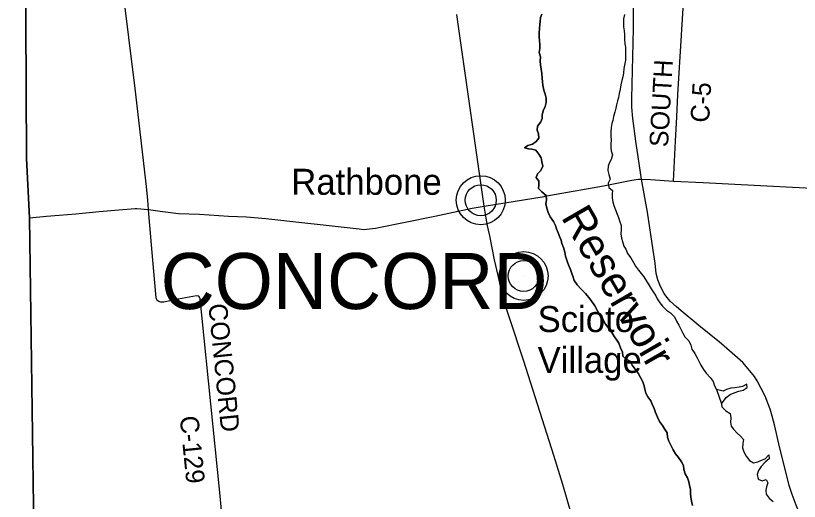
# Model space of a CAD drawing. Extents: x 1674899 to 2057726, y 653888 to 988278.
# Drawn here: x 1780755 to 1793352, y 795806 to 803604 of the extents above; entities that cross this region are included whole.
import ezdxf

# ---------------------------------------------------------------- set-up
doc = ezdxf.new("R2010")
doc.units = 0
for name, color, linetype in [('GM_X_Adjacent_County', 7, 'Continuous'), ('GM_X_County', 7, 'Continuous'), ('GM_X_County_Road', 7, 'Continuous'), ('GM_X_County_Road_Text', 7, 'Continuous'), ('GM_X_Major_Lake', 7, 'Continuous'), ('GM_X_Major_Lake_Text', 7, 'Continuous'), ('GM_X_Major_River', 7, 'Continuous'), ('GM_X_State_Route', 7, 'Continuous'), ('GM_X_Township', 7, 'Continuous'), ('GM_X_Township_Text', 7, 'Continuous'), ('GM_X_Unincorporated', 7, 'Continuous'), ('GM_X_Unincorporated_Location', 7, 'Continuous'), ('GM_X_Unincorporated_Text', 7, 'Continuous')]:
    doc.layers.add(name, color=color, linetype=linetype)

msp = doc.modelspace()

# ---------------------------------------------------------------- linework, layer by layer
at = {"layer": 'GM_X_Adjacent_County'}
msp.add_lwpolyline([(1780755, 818148), (1780889, 810163), (1780895, 808002), (1780927, 801312), (1780979, 800357), (1781040, 795733), (1781062, 793102), (1781083, 789921), (1781088, 789265), (1781086, 787507), (1781084, 787075), (1781136, 786470), (1781151, 786236), (1781162, 786094), (1781118, 783904)], dxfattribs=at)
at = {"layer": 'GM_X_County'}
msp.add_lwpolyline([(1781118, 783904), (1781162, 786094), (1781151, 786236), (1781136, 786470), (1781084, 787075), (1781086, 787507), (1781088, 789265), (1781083, 789921), (1781062, 793102), (1781040, 795733), (1780979, 800357), (1780927, 801312), (1780895, 808002), (1780889, 810163), (1780755, 818148)], dxfattribs=at)
at = {"layer": 'GM_X_County_Road'}
for points in [[(1782890, 800490), (1782881, 800644), (1782856, 800863), (1782676, 802437), (1782464, 804119), (1782395, 804661), (1782246, 805871), (1782006, 808105), (1781669, 811078), (1781659, 811109), (1781650, 811131), (1781636, 811151)], [(1791328, 800949), (1791359, 801588), (1791381, 801980), (1791400, 802336), (1791517, 804248), (1791555, 804839), (1791576, 805255), (1791663, 806861), (1791666, 806898), (1791673, 806996), (1791713, 807764)], [(1790259, 800884), (1790662, 800965), (1790767, 800980), (1790816, 800981)], [(1790816, 800981), (1790957, 800973), (1791328, 800949), (1791805, 800926), (1792317, 800900), (1794586, 800781), (1795455, 800738), (1796520, 800687)], [(1789248, 800701), (1789260, 800704), (1790202, 800872), (1790259, 800884)], [(1788284, 800545), (1789248, 800701)], [(1780979, 800357), (1781251, 800385), (1781456, 800401), (1781721, 800423), (1782095, 800460), (1782415, 800484), (1782676, 800509), (1782703, 800508), (1782890, 800490), (1783080, 800464), (1783370, 800430), (1783710, 800417), (1784177, 800386), (1784465, 800376), (1784774, 800347), (1786277, 800180), (1786348, 800171), (1786537, 800193), (1787491, 800386), (1788093, 800511), (1788252, 800542), (1788284, 800545)], [(1784231, 794169), (1784213, 794320), (1784208, 794381), (1784184, 794592), (1784065, 795658), (1784036, 795945), (1783745, 798796), (1783719, 799058), (1783710, 799082), (1783697, 799100), (1783664, 799103), (1783307, 799040), (1783135, 799003), (1783086, 799003), (1783057, 799012), (1783029, 799032), (1783012, 799071), (1782957, 799680), (1782900, 800360), (1782890, 800490)]]:
    msp.add_lwpolyline(points, dxfattribs=at)
at = {"layer": 'GM_X_Major_Lake'}
msp.add_line((1792018, 797602), (1792101, 797371), dxfattribs=at)
for points in [[(1790667, 797990), (1790633, 798055), (1790567, 798091), (1790513, 798137), (1790511, 798203), (1790479, 798271), (1790448, 798346), (1790416, 798396), (1790370, 798464), (1790340, 798516), (1790290, 798580), (1790238, 798649), (1790199, 798721), (1790153, 798789), (1790105, 798865), (1790063, 798946), (1790019, 799012), (1789966, 799078), (1789912, 799141), (1789846, 799215), (1789778, 799283), (1789730, 799350), (1789714, 799404), (1789695, 799464), (1789673, 799526), (1789651, 799578), (1789631, 799628), (1789607, 799694), (1789594, 799744), (1789582, 799809), (1789560, 799879), (1789536, 799947), (1789521, 799997), (1789503, 800047), (1789475, 800115), (1789451, 800179), (1789435, 800236), (1789398, 800300), (1789344, 800372), (1789316, 800444), (1789294, 800515), (1789275, 800583), (1789287, 800649), (1789281, 800717), (1789213, 800773), (1789161, 800827), (1789166, 800884), (1789164, 800948), (1789120, 801008), (1789144, 801062), (1789195, 801120), (1789229, 801186), (1789215, 801256), (1789200, 801320), (1789162, 801380), (1789118, 801446), (1789050, 801463), (1789000, 801465), (1788934, 801483), (1788990, 801519), (1789062, 801541), (1789123, 801585), (1789167, 801638), (1789159, 801705), (1789135, 801767), (1789144, 801831), (1789196, 801901), (1789216, 801955), (1789217, 802007), (1789235, 802077), (1789267, 802143), (1789284, 802211), (1789280, 802277), (1789264, 802341), (1789247, 802409), (1789229, 802487), (1789223, 802539), (1789217, 802603), (1789210, 802676), (1789204, 802744), (1789190, 802814), (1789186, 802876), (1789189, 802944), (1789171, 803010), (1789181, 803078), (1789182, 803142), (1789176, 803207), (1789172, 803259), (1789172, 803325), (1789175, 803397), (1789181, 803461), (1789185, 803511), (1789193, 803573), (1789210, 803629)], [(1790543, 803625), (1790525, 803553), (1790525, 803475), (1790528, 803423), (1790536, 803360), (1790542, 803302), (1790544, 803224), (1790549, 803152), (1790557, 803100), (1790559, 803028), (1790558, 802962), (1790556, 802890), (1790542, 802808), (1790531, 802756), (1790525, 802681), (1790517, 802621), (1790499, 802565), (1790480, 802493), (1790470, 802423), (1790456, 802355), (1790443, 802291), (1790431, 802239), (1790415, 802171), (1790402, 802121), (1790384, 802055), (1790366, 801985), (1790355, 801923), (1790337, 801873), (1790329, 801809), (1790324, 801737), (1790324, 801667), (1790326, 801599), (1790324, 801549), (1790323, 801483), (1790327, 801431), (1790347, 801367), (1790325, 801295), (1790302, 801245), (1790280, 801187), (1790274, 801117), (1790289, 801052), (1790309, 800978), (1790281, 800912), (1790292, 800844), (1790348, 800798), (1790344, 800744), (1790344, 800676), (1790352, 800614), (1790371, 800556), (1790395, 800487), (1790425, 800417), (1790447, 800363), (1790462, 800309), (1790486, 800233), (1790488, 800171), (1790480, 800101), (1790493, 800032), (1790509, 799978), (1790531, 799902), (1790561, 799852), (1790588, 799786), (1790642, 799716), (1790684, 799641), (1790718, 799583), (1790764, 799515), (1790810, 799463), (1790851, 799408), (1790897, 799342), (1790931, 799284), (1790971, 799220), (1791003, 799167), (1791043, 799107), (1791068, 799057), (1791108, 798995), (1791154, 798939)], [(1791154, 798939), (1791218, 798876), (1791282, 798832), (1791346, 798770), (1791378, 798701), (1791417, 798637), (1791453, 798557), (1791477, 798505), (1791511, 798445), (1791575, 798382), (1791606, 798312), (1791626, 798248), (1791670, 798178), (1791712, 798110), (1791744, 798043), (1791767, 797991), (1791809, 797923), (1791855, 797863), (1791919, 797792), (1791965, 797732), (1791989, 797662), (1792018, 797602)], [(1791635, 795739), (1791617, 795809), (1791609, 795873), (1791604, 795931), (1791600, 795997), (1791586, 796065), (1791576, 796117), (1791553, 796183), (1791517, 796248), (1791493, 796316), (1791491, 796380), (1791458, 796442), (1791412, 796508), (1791364, 796571), (1791324, 796635), (1791284, 796709), (1791252, 796771), (1791233, 796835), (1791225, 796903), (1791185, 796972), (1791151, 797022), (1791106, 797090), (1791072, 797156), (1791042, 797230), (1791016, 797294), (1790984, 797365), (1790965, 797417), (1790917, 797483), (1790885, 797543), (1790867, 797607), (1790858, 797661), (1790836, 797725), (1790798, 797794), (1790762, 797862), (1790712, 797926), (1790667, 797990)], [(1792101, 797371), (1792105, 797321), (1792171, 797259), (1792239, 797217), (1792251, 797149), (1792243, 797079), (1792258, 797015), (1792292, 796964), (1792352, 796900), (1792408, 796850), (1792454, 796798), (1792443, 796732), (1792441, 796666), (1792459, 796603), (1792499, 796531), (1792551, 796461), (1792615, 796425), (1792683, 796442), (1792745, 796466), (1792803, 796486), (1792860, 796552), (1792865, 796488), (1792801, 796434), (1792741, 796366), (1792694, 796302), (1792674, 796234), (1792692, 796162), (1792754, 796136), (1792820, 796154), (1792846, 796103), (1792825, 796038), (1792813, 795986), (1792821, 795919), (1792867, 795855), (1792929, 795803)]]:
    msp.add_lwpolyline(points, dxfattribs=at)
at = {"layer": 'GM_X_Major_River'}
msp.add_line((1792018, 797602), (1792101, 797371), dxfattribs=at)
for points in [[(1789210, 803629), (1789193, 803573), (1789185, 803511), (1789181, 803461), (1789175, 803397), (1789172, 803325), (1789172, 803259), (1789176, 803207), (1789182, 803142), (1789181, 803078), (1789171, 803010), (1789189, 802944), (1789186, 802876), (1789190, 802814), (1789204, 802744), (1789210, 802676), (1789217, 802603), (1789223, 802539), (1789229, 802487), (1789247, 802409), (1789264, 802341), (1789280, 802277), (1789284, 802211), (1789267, 802143), (1789235, 802077), (1789217, 802007), (1789216, 801955), (1789196, 801901), (1789144, 801831), (1789135, 801767), (1789159, 801705), (1789167, 801638), (1789123, 801585), (1789062, 801541), (1788990, 801519), (1788934, 801483), (1789000, 801465), (1789050, 801463), (1789118, 801446), (1789162, 801380), (1789200, 801320), (1789215, 801256), (1789229, 801186), (1789195, 801120), (1789144, 801062), (1789120, 801008), (1789164, 800948), (1789166, 800884), (1789161, 800827), (1789213, 800773), (1789281, 800717), (1789287, 800649), (1789275, 800583), (1789294, 800515), (1789316, 800444), (1789344, 800372), (1789398, 800300), (1789435, 800236), (1789451, 800179), (1789475, 800115), (1789503, 800047), (1789521, 799997), (1789536, 799947), (1789560, 799879), (1789582, 799809), (1789594, 799744), (1789607, 799694), (1789631, 799628), (1789651, 799578), (1789673, 799526), (1789695, 799464), (1789714, 799404), (1789730, 799350), (1789778, 799283), (1789846, 799215), (1789912, 799141), (1789966, 799078), (1790019, 799012), (1790063, 798946), (1790105, 798865), (1790153, 798789), (1790199, 798721), (1790238, 798649), (1790290, 798580), (1790340, 798516), (1790370, 798464), (1790416, 798396), (1790448, 798346), (1790479, 798271), (1790511, 798203), (1790513, 798137), (1790567, 798091), (1790633, 798055), (1790667, 797990)], [(1790543, 803625), (1790525, 803553), (1790525, 803475), (1790528, 803423), (1790536, 803360), (1790542, 803302), (1790544, 803224), (1790549, 803152), (1790557, 803100), (1790559, 803028), (1790558, 802962), (1790556, 802890), (1790542, 802808), (1790531, 802756), (1790525, 802681), (1790517, 802621), (1790499, 802565), (1790480, 802493), (1790470, 802423), (1790456, 802355), (1790443, 802291), (1790431, 802239), (1790415, 802171), (1790402, 802121), (1790384, 802055), (1790366, 801985), (1790355, 801923), (1790337, 801873), (1790329, 801809), (1790324, 801737), (1790324, 801667), (1790326, 801599), (1790324, 801549), (1790323, 801483), (1790327, 801431), (1790347, 801367), (1790325, 801295), (1790302, 801245), (1790280, 801187), (1790274, 801117), (1790289, 801052), (1790309, 800978), (1790281, 800912), (1790292, 800844), (1790348, 800798), (1790344, 800744), (1790344, 800676), (1790352, 800614), (1790371, 800556), (1790395, 800487), (1790425, 800417), (1790447, 800363), (1790462, 800309), (1790486, 800233), (1790488, 800171), (1790480, 800101), (1790493, 800032), (1790509, 799978), (1790531, 799902), (1790561, 799852), (1790588, 799786), (1790642, 799716), (1790684, 799641), (1790718, 799583), (1790764, 799515), (1790810, 799463), (1790851, 799408), (1790897, 799342), (1790931, 799284), (1790971, 799220), (1791003, 799167), (1791043, 799107), (1791068, 799057), (1791108, 798995), (1791154, 798939)], [(1791154, 798939), (1791218, 798876), (1791282, 798832), (1791346, 798770), (1791378, 798701), (1791417, 798637), (1791453, 798557), (1791477, 798505), (1791511, 798445), (1791575, 798382), (1791606, 798312), (1791626, 798248), (1791670, 798178), (1791712, 798110), (1791744, 798043), (1791767, 797991), (1791809, 797923), (1791855, 797863), (1791919, 797792), (1791965, 797732), (1791989, 797662), (1792018, 797602)], [(1790667, 797990), (1790712, 797926), (1790762, 797862), (1790798, 797794), (1790836, 797725), (1790858, 797661), (1790867, 797607), (1790885, 797543), (1790917, 797483), (1790965, 797417), (1790984, 797365), (1791016, 797294), (1791042, 797230), (1791072, 797156), (1791106, 797090), (1791151, 797022), (1791185, 796972), (1791225, 796903), (1791233, 796835), (1791252, 796771), (1791284, 796709), (1791324, 796635), (1791364, 796571), (1791412, 796508), (1791458, 796442), (1791491, 796380), (1791493, 796316), (1791517, 796248), (1791553, 796183), (1791576, 796117), (1791586, 796065), (1791600, 795997), (1791604, 795931), (1791609, 795873), (1791617, 795809), (1791635, 795739)], [(1792101, 797371), (1792178, 797472), (1792238, 797522), (1792303, 797550), (1792379, 797572), (1792447, 797592), (1792513, 797635), (1792510, 797685), (1792439, 797652), (1792387, 797638), (1792315, 797630), (1792253, 797624), (1792183, 797604), (1792128, 797572), (1792018, 797602)], [(1792101, 797371), (1792105, 797321), (1792171, 797259), (1792239, 797217), (1792251, 797149), (1792243, 797079), (1792258, 797015), (1792292, 796964), (1792352, 796900), (1792408, 796850), (1792454, 796798), (1792443, 796732), (1792441, 796666), (1792459, 796603), (1792499, 796531), (1792551, 796461), (1792615, 796425), (1792683, 796442), (1792745, 796466), (1792803, 796486), (1792860, 796552), (1792865, 796488), (1792801, 796434), (1792741, 796366), (1792694, 796302), (1792674, 796234), (1792692, 796162), (1792754, 796136), (1792820, 796154), (1792846, 796103), (1792825, 796038), (1792813, 795986), (1792821, 795919), (1792867, 795855), (1792929, 795803)]]:
    msp.add_lwpolyline(points, dxfattribs=at)
at = {"layer": 'GM_X_State_Route'}
for points in [[(1790684, 803416), (1790687, 803933), (1790683, 804011), (1790681, 804061), (1790677, 804093)], [(1789691, 795593), (1789552, 796074), (1789406, 796539), (1788925, 798054), (1788685, 798770), (1788593, 799061), (1788574, 799137), (1788559, 799211), (1788513, 799432), (1788454, 799683), (1788376, 800070), (1788357, 800160), (1788339, 800233), (1788316, 800352), (1788284, 800545), (1788263, 800693), (1787872, 803431), (1787846, 803622)], [(1790816, 800981), (1790725, 801587), (1790674, 801951), (1790662, 802137), (1790662, 802272), (1790684, 803396), (1790684, 803416)], [(1792099, 798333), (1792069, 798359), (1791739, 798628), (1791453, 798865), (1791371, 798933), (1791282, 799017), (1791224, 799083), (1791180, 799145), (1791143, 799214), (1791110, 799281), (1791078, 799363), (1791051, 799466), (1791032, 799632), (1791000, 799840), (1790910, 800451), (1790816, 800981)], [(1793626, 794462), (1793626, 794462), (1793641, 794594), (1793644, 794648), (1793641, 794771), (1793623, 794897), (1793613, 794945), (1793580, 795059), (1793566, 795094), (1793498, 795270), (1793303, 795745), (1793237, 795913), (1793188, 796062), (1793091, 796453), (1793034, 796681), (1792957, 797013), (1792916, 797174), (1792881, 797288), (1792802, 797495), (1792672, 797742), (1792629, 797811), (1792556, 797903), (1792444, 798033), (1792099, 798333)]]:
    msp.add_lwpolyline(points, dxfattribs=at)
at = {"layer": 'GM_X_Township'}
msp.add_lwpolyline([(1781118, 783904), (1781162, 786094), (1781151, 786236), (1781136, 786470), (1781084, 787075), (1781086, 787507), (1781088, 789265), (1781083, 789921), (1781062, 793102), (1781040, 795733), (1780979, 800357), (1780927, 801312), (1780895, 808002), (1780889, 810163), (1780755, 818148)], dxfattribs=at)
at = {"layer": 'GM_X_Unincorporated'}
for centre, radius in [((1788231, 800641), 393), ((1788231, 800641), 249), ((1788921, 799424), 393), ((1788921, 799424), 249)]:
    msp.add_circle(centre, radius, dxfattribs=at)
at = {"layer": 'GM_X_Unincorporated_Location'}
for p, q in [((1788231, 800641), (1788231, 800641)), ((1788921, 799424), (1788921, 799424))]:
    msp.add_line(p, q, dxfattribs=at)

# ---------------------------------------------------------------- texts
at = {"layer": 'GM_X_County_Road_Text'}
for s, rotation, p in [('SOUTH', 86.6936, (1791240, 801487)), ('C-5', 86.8, (1791901, 801881)), ('CONCORD', 275.7674, (1783851, 798968)), ('C-129', 275.7928, (1783391, 797165))]:
    msp.add_text(s, height=300, rotation=rotation, dxfattribs=at).set_placement(p)
at = {"layer": 'GM_X_Major_Lake_Text'}
msp.add_text('Reservoir', height=499.3, rotation=300.0355, dxfattribs=at).set_placement((1789514, 800369))
at = {"layer": 'GM_X_Township_Text'}
msp.add_text('CONCORD', height=900, rotation=0, dxfattribs=at).set_placement((1783085, 798893))
at = {"layer": 'GM_X_Unincorporated_Text'}
for s, p in [('Rathbone', (1785185, 800728)), ('Scioto', (1789145, 798524)), ('Village', (1789145, 797868))]:
    msp.add_text(s, height=417, rotation=0, dxfattribs=at).set_placement(p)

doc.saveas('drawing.dxf')
